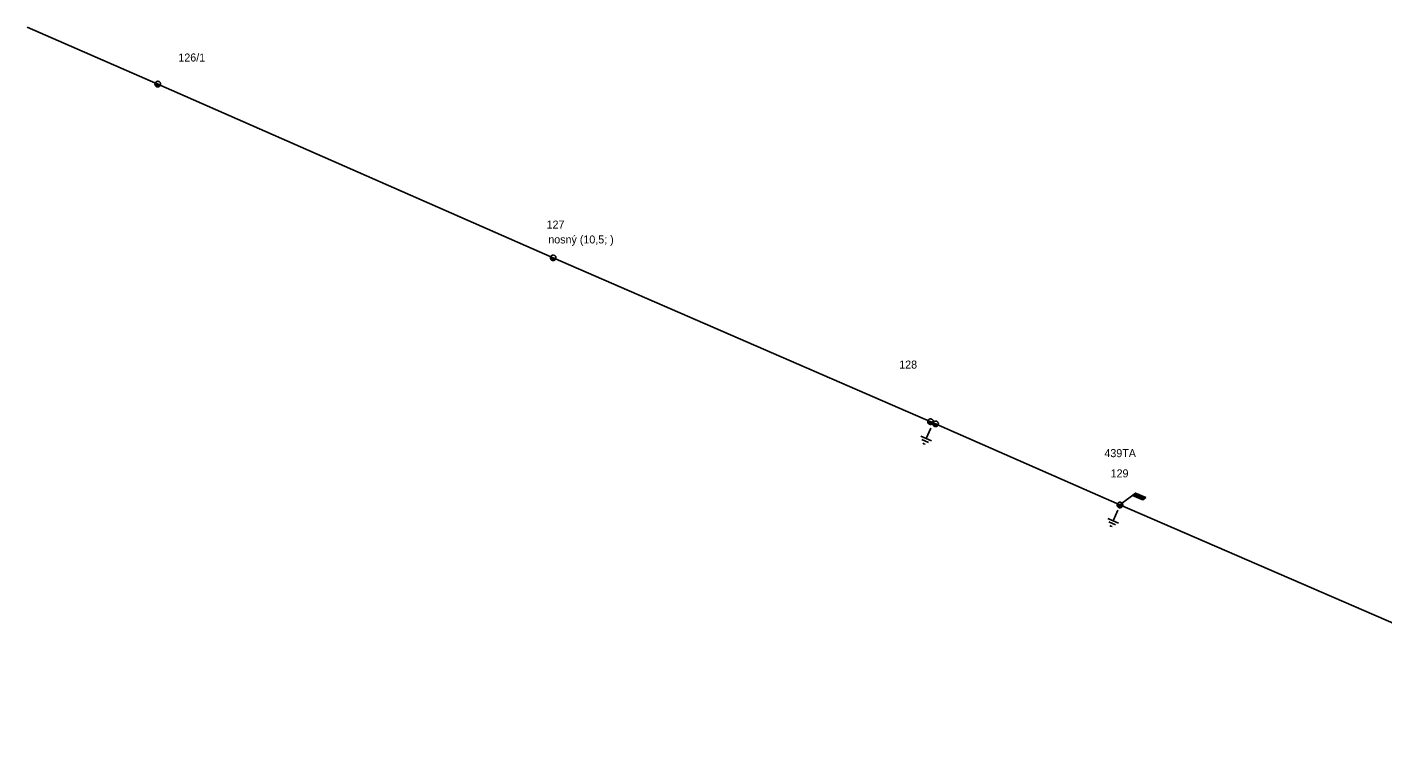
# Model space of a CAD drawing. Extents: x -737463 to -734268, y -1145636 to -1142570.
# Drawn here: x -737040.6 to -736744.1, y -1144257 to -1144099 of the extents above; entities that cross this region are included whole.
import ezdxf

# ---------------------------------------------------------------- set-up
doc = ezdxf.new("R2010")
doc.units = 0
for name, color, linetype in [('Vrstva 1', 7, 'Continuous'), ('Vrstva 11', 7, 'Continuous'), ('Vrstva 12', 7, 'Continuous'), ('Vrstva 13', 7, 'Continuous'), ('Vrstva 14', 7, 'Continuous'), ('Vrstva 15', 7, 'Continuous'), ('Vrstva 2', 7, 'Continuous'), ('Vrstva 3', 7, 'Continuous'), ('Vrstva 49', 7, 'Continuous')]:
    doc.layers.add(name, color=color, linetype=linetype)

# ---------------------------------------------------------------- blocks, each defined once
blk = doc.blocks.new('VN440')
at = {"layer": 'Vrstva 2'}
for points in [[(1.22, 0), (1.21, 0.13), (1.19, 0.25), (1.16, 0.38), (1.11, 0.5), (1.05, 0.61), (0.98, 0.72), (0.9, 0.82), (0.81, 0.91), (0.71, 0.99), (0.6, 1.06), (0.49, 1.12), (0.37, 1.16), (0.25, 1.2), (0.12, 1.22), (-0.01, 1.22), (-0.14, 1.22), (-0.26, 1.2), (-0.39, 1.16), (-0.51, 1.12), (-0.62, 1.06), (-0.73, 0.99), (-0.83, 0.91), (-0.92, 0.82), (-1, 0.72), (-1.07, 0.61), (-1.13, 0.5), (-1.18, 0.38), (-1.21, 0.25), (-1.23, 0.13), (-1.24, 0), (-1.23, -0.13), (-1.21, -0.26), (-1.18, -0.38), (-1.13, -0.5), (-1.07, -0.62), (-1, -0.73), (-0.92, -0.83), (-0.83, -0.92), (-0.73, -1), (-0.62, -1.07), (-0.51, -1.13), (-0.39, -1.17), (-0.26, -1.2), (-0.14, -1.23), (-0.01, -1.23), (0.12, -1.23), (0.25, -1.2), (0.37, -1.17), (0.49, -1.13), (0.6, -1.07), (0.71, -1), (0.81, -0.92), (0.9, -0.83), (0.98, -0.73), (1.05, -0.62), (1.11, -0.5), (1.16, -0.38), (1.19, -0.26), (1.21, -0.13), (1.22, 0)], [(-1.24, 0), (1.22, 0)], [(-1.18, -0.34), (1.1, -0.34)], [(-1.01, -0.63), (0.97, -0.63)], [(-0.74, -0.92), (0.68, -0.92)]]:
    blk.add_lwpolyline(points, dxfattribs=at)
blk = doc.blocks.new('VN810')
at = {"layer": 'Vrstva 14'}
for points in [[(0, -1.25), (0, -3.75)], [(1.25, -3.75), (-1.25, -3.75)], [(0.77, -4.37), (-0.8, -4.37)], [(0, -5), (-0.25, -5)], [(0.27, -5), (0, -5)]]:
    blk.add_lwpolyline(points, dxfattribs=at)
blk = doc.blocks.new('VN450')
at = {"layer": 'Vrstva 2'}
for points in [[(0, 0), (-0.01, 0.13), (-0.03, 0.25), (-0.06, 0.38), (-0.11, 0.5), (-0.16, 0.61), (-0.23, 0.72), (-0.31, 0.82), (-0.4, 0.91), (-0.5, 0.99), (-0.61, 1.06), (-0.72, 1.11), (-0.84, 1.16), (-0.97, 1.19), (-1.09, 1.21), (-1.22, 1.22), (-1.35, 1.21), (-1.47, 1.19), (-1.59, 1.16), (-1.71, 1.11), (-1.83, 1.06), (-1.93, 0.99), (-2.03, 0.91), (-2.12, 0.82), (-2.2, 0.72), (-2.27, 0.61), (-2.33, 0.5), (-2.38, 0.38), (-2.41, 0.25), (-2.43, 0.13), (-2.44, 0), (-2.43, -0.13), (-2.41, -0.25), (-2.38, -0.38), (-2.33, -0.5), (-2.27, -0.61), (-2.2, -0.72), (-2.12, -0.82), (-2.03, -0.91), (-1.93, -0.99), (-1.83, -1.06), (-1.71, -1.11), (-1.59, -1.16), (-1.47, -1.19), (-1.35, -1.21), (-1.22, -1.22), (-1.09, -1.21), (-0.97, -1.19), (-0.84, -1.16), (-0.72, -1.11), (-0.61, -1.06), (-0.5, -0.99), (-0.4, -0.91), (-0.31, -0.82), (-0.23, -0.72), (-0.16, -0.61), (-0.11, -0.5), (-0.06, -0.38), (-0.03, -0.25), (-0.01, -0.13), (0, 0)], [(-2.44, 0), (2.44, 0)], [(2.44, 0), (2.43, 0.13), (2.41, 0.25), (2.38, 0.38), (2.33, 0.5), (2.27, 0.61), (2.2, 0.72), (2.12, 0.82), (2.03, 0.91), (1.94, 0.99), (1.83, 1.06), (1.71, 1.11), (1.6, 1.16), (1.47, 1.19), (1.35, 1.21), (1.22, 1.22), (1.09, 1.21), (0.97, 1.19), (0.84, 1.16), (0.72, 1.11), (0.61, 1.06), (0.5, 0.99), (0.4, 0.91), (0.31, 0.82), (0.23, 0.72), (0.16, 0.61), (0.11, 0.5), (0.06, 0.38), (0.03, 0.25), (0.01, 0.13), (0, 0), (0.01, -0.13), (0.03, -0.25), (0.06, -0.38), (0.11, -0.5), (0.16, -0.61), (0.23, -0.72), (0.31, -0.82), (0.4, -0.91), (0.5, -0.99), (0.61, -1.06), (0.72, -1.11), (0.84, -1.16), (0.97, -1.19), (1.09, -1.21), (1.22, -1.22), (1.35, -1.21), (1.47, -1.19), (1.6, -1.16), (1.71, -1.11), (1.83, -1.06), (1.94, -0.99), (2.03, -0.91), (2.12, -0.82), (2.2, -0.72), (2.27, -0.61), (2.33, -0.5), (2.38, -0.38), (2.41, -0.25), (2.43, -0.13), (2.44, 0)], [(-2.4, -0.31), (-0.04, -0.31)], [(-2.26, -0.61), (-0.17, -0.61)], [(-2.01, -0.92), (-0.42, -0.92)], [(0.04, -0.31), (2.4, -0.31)], [(0.17, -0.61), (2.27, -0.61)], [(0.42, -0.92), (2.02, -0.92)]]:
    blk.add_lwpolyline(points, dxfattribs=at)
blk = doc.blocks.new('VN001')
at = {"layer": 'Vrstva 3'}
for p, q in [((1.71, 3), (4.14, 3)), ((1.72, 3.02), (4.15, 3.02)), ((1.73, 3.04), (4.16, 3.04)), ((1.74, 3.06), (4.17, 3.06)), ((1.76, 3.08), (4.19, 3.08)), ((1.77, 3.1), (4.2, 3.1)), ((1.78, 3.12), (4.21, 3.12)), ((1.79, 3.14), (4.22, 3.14)), ((1.8, 3.16), (4.24, 3.16)), ((1.81, 3.18), (4.25, 3.18)), ((1.83, 3.2), (4.26, 3.2)), ((1.84, 3.22), (4.27, 3.22)), ((1.85, 3.24), (4.29, 3.24)), ((1.86, 3.26), (4.3, 3.26)), ((1.87, 3.28), (4.31, 3.28)), ((1.88, 3.3), (4.32, 3.3)), ((1.9, 3.32), (4.34, 3.32)), ((1.91, 3.34), (4.35, 3.34)), ((1.92, 3.36), (4.36, 3.36)), ((1.93, 3.38), (4.37, 3.38)), ((1.94, 3.4), (4.39, 3.4)), ((1.95, 3.42), (4.4, 3.42)), ((1.96, 3.44), (4.41, 3.44)), ((1.98, 3.46), (4.42, 3.46)), ((1.99, 3.48), (4.44, 3.48)), ((2, 3.5), (4.45, 3.5)), ((2.01, 3.52), (4.46, 3.52)), ((2.02, 3.54), (4.47, 3.54)), ((2.03, 3.56), (4.49, 3.56)), ((2.05, 3.58), (4.5, 3.58)), ((2.06, 3.6), (4.51, 3.6)), ((2.07, 3.62), (4.52, 3.62)), ((2.08, 3.64), (4.54, 3.64)), ((2.09, 3.66), (4.55, 3.66)), ((2.1, 3.68), (4.56, 3.68)), ((2.11, 3.7), (4.57, 3.7)), ((2.13, 3.73), (4.59, 3.73)), ((2.13, 3.72), (4.59, 3.72))]:
    blk.add_line(p, q, dxfattribs=at)
blk.add_lwpolyline([(2.13, 3.73), (0, 0)], dxfattribs=at)
blk.add_lwpolyline([(4.59, 3.73), (2.13, 3.73), (1.7, 2.99), (4.13, 2.99)], close=True, dxfattribs=at)

msp = doc.modelspace()

# ---------------------------------------------------------------- linework, layer by layer
at = {"layer": 'Vrstva 1'}
for points in [[(-736801.57, -1144203.49), (-736842.45, -1144185.51), (-736925.52, -1144149.44), (-737011.99, -1144111.46), (-737040.57, -1144099)], [(-736678.15, -1144257.04), (-736734.06, -1144232.71), (-736801.57, -1144203.49)]]:
    msp.add_lwpolyline(points, dxfattribs=at)

# ---------------------------------------------------------------- block references
at = {"layer": 'Vrstva 11', "rotation": -23.091038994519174}
msp.add_blockref('VN001', (-736801.57, -1144203.49), dxfattribs=at)
at = {"layer": 'Vrstva 13'}
for name, p, xscale, yscale, rotation in [('VN440', (-737011.99, -1144111.46), 0.49999999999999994, 0.5000000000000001, -23.366969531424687), ('VN440', (-736925.52, -1144149.44), 0.5000000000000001, 0.5, -23.63597865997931), ('VN450', (-736842.45, -1144185.51), 0.5000000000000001, 0.5, -23.36696950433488), ('VN440', (-736801.57, -1144203.49), 0.49999999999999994, 0.5, -23.091038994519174)]:
    msp.add_blockref(name, p, dxfattribs=dict(at, xscale=xscale, yscale=yscale, rotation=rotation))
at = {"layer": 'Vrstva 15'}
for p, rotation in [((-736842.45, -1144185.51), -23.36696950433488), ((-736801.57, -1144203.49), -23.091038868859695)]:
    msp.add_blockref('VN810', p, dxfattribs=dict(at, rotation=rotation))

# ---------------------------------------------------------------- texts
at = {"layer": 'Vrstva 12'}
msp.add_text('439TA', height=1.75, dxfattribs=at).set_placement((-736804.97, -1144193.03))
at = {"layer": 'Vrstva 14'}
for s, p in [('126/1', (-737007.49, -1144106.52)), ('127', (-736926.96, -1144143.05)), ('128', (-736849.84, -1144173.66)), ('129', (-736803.61, -1144197.45))]:
    msp.add_text(s, height=1.75, dxfattribs=at).set_placement(p)
at = {"layer": 'Vrstva 49'}
msp.add_text('nosný (10,5; )', height=1.75, dxfattribs=at).set_placement((-736926.59, -1144146.3))

doc.saveas('drawing.dxf')
